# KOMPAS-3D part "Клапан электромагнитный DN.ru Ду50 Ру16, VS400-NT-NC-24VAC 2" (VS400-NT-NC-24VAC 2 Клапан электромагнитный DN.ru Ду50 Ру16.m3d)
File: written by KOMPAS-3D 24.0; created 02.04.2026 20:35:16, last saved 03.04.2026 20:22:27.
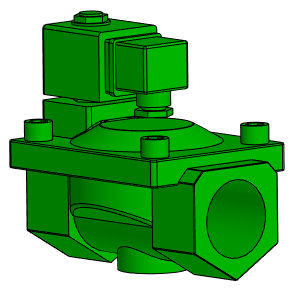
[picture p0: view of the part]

Document properties: Автор: artio; Полное имя файла: C:\Users\artio\OneDrive\Рабочий стол\Клапан электромагнитный DN.ru\VS400-NT-NC\VS400-NT-NC-24VAC 2 Клапан электромагнитный DN.ru Ду50 Ру16.m3d

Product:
- Body: Тело 1  | qty 1
    Масса: 7.119215
- Part/product: Клапан электромагнитный DN.ru Ду50 Ру16  | designation VS400-NT-NC-24VAC 2
    Масса: 3.509
    Раздел спецификации: Прочие изделия
    Примечание: D130-05497
    additional columns: ef56311e-7521-43dc-8291-0e6108b3d81d; VS400-ET-NC-220VAC 2; artio; c; Шероховатость не задана; Да

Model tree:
1. Операция без истории:1

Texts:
  VS400-NT-NC-24VAC 2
